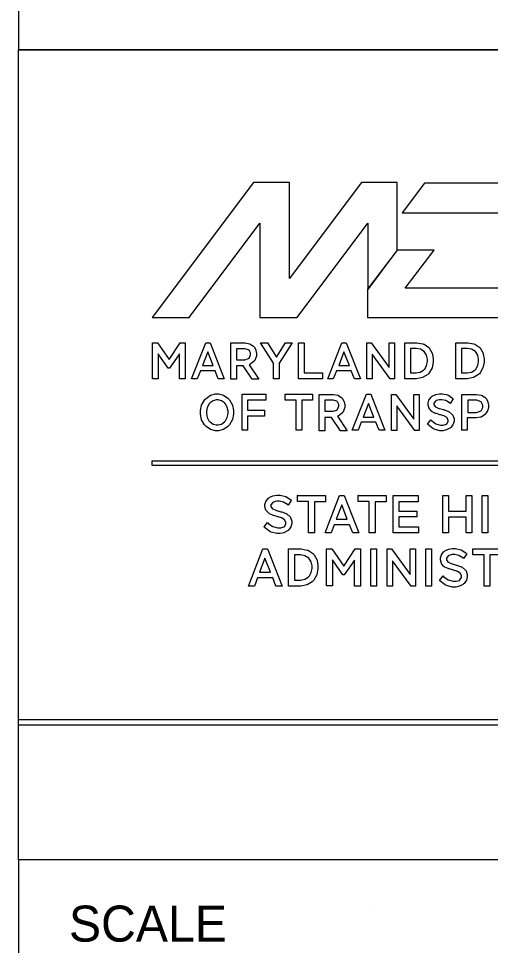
# Model space of a CAD drawing. Extents: x 0 to 34, y 0 to 22.
# Drawn here: x 27.437 to 28.747, y 2.513 to 5.087 of the extents above; entities that cross this region are included whole.
import ezdxf

# ---------------------------------------------------------------- set-up
doc = ezdxf.new("R2010")
doc.units = 0
for name, color, linetype in [('BORD-LINE', 7, 'Continuous'), ('MSHA-LOGO', 7, 'Continuous'), ('QNTY-LINE', 7, 'Continuous'), ('TTLB-TEXT', 7, 'Continuous'), ('USER-LINE', 7, 'Continuous')]:
    doc.layers.add(name, color=color, linetype=linetype)

msp = doc.modelspace()

# ---------------------------------------------------------------- linework, layer by layer
at = {"layer": 'BORD-LINE'}
for p, q in [((33.5, 5), (27.437, 5)), ((27.437, 2.75), (27.437, 5)), ((27.437, 2.75), (27.437, 0.75)), ((33.5, 2.75), (27.437, 2.75))]:
    msp.add_line(p, q, dxfattribs=at)
msp.add_lwpolyline([(27.437, 2.75), (27.437, 3.125), (33.5, 3.125)], dxfattribs=at)
at = {"layer": 'MSHA-LOGO'}
for points in [[(28.4067, 4.3335), (28.4886, 4.4423), (28.4886, 4.631), (28.389, 4.631), (28.3274, 4.5486), (28.189, 4.3646), (28.189, 4.631), (28.0895, 4.631), (27.8081, 4.2568), (27.9107, 4.2568), (28.1071, 4.518), (28.1071, 4.2568), (28.2102, 4.2568), (28.4067, 4.518)], [(27.8086, 4.1863), (27.8226, 4.1863), (27.8547, 4.1397), (27.8858, 4.1863), (27.8993, 4.1863), (27.8993, 4.0863), (27.8838, 4.0863), (27.8838, 4.1557), (27.8563, 4.1158), (27.8521, 4.1158), (27.8242, 4.1557), (27.8242, 4.0863), (27.8086, 4.0863)], [(27.9568, 4.1863), (27.9688, 4.1863), (28.0081, 4.0863), (27.9916, 4.0863), (27.9827, 4.1086), (27.9418, 4.1086), (27.933, 4.0863), (27.9169, 4.0863)], [(28.0263, 4.0858), (28.0263, 4.1858), (28.0615, 4.1858), (28.0659, 4.1858), (28.0779, 4.1836), (28.0792, 4.1832), (28.0803, 4.1828), (28.0894, 4.1767), (28.09, 4.176), (28.0907, 4.1752), (28.0953, 4.167), (28.0957, 4.1661), (28.096, 4.1652), (28.0973, 4.1569), (28.0973, 4.1542), (28.0973, 4.1497), (28.093, 4.1374), (28.0921, 4.1361), (28.0912, 4.1348), (28.0791, 4.1257), (28.0776, 4.1252), (28.1045, 4.0853), (28.0854, 4.0853), (28.061, 4.122), (28.0418, 4.122), (28.0418, 4.0853), (28.0263, 4.0853)], [(28.1605, 4.1293), (28.1605, 4.0858), (28.145, 4.0858), (28.145, 4.1293), (28.1087, 4.1863), (28.1278, 4.1863), (28.1527, 4.1464), (28.1781, 4.1863), (28.1968, 4.1863)], [(28.2144, 4.1863), (28.23, 4.1863), (28.23, 4.1024), (28.2813, 4.1024), (28.2813, 4.0863), (28.2144, 4.0863)], [(28.3346, 4.1863), (28.3466, 4.1863), (28.3859, 4.0863), (28.3694, 4.0863), (28.3605, 4.1086), (28.3196, 4.1086), (28.3108, 4.0863), (28.2952, 4.0863)], [(28.4689, 4.0858), (28.4191, 4.1542), (28.4191, 4.0858), (28.4041, 4.0858), (28.4041, 4.1858), (28.416, 4.1858), (28.4658, 4.1174), (28.4658, 4.1858), (28.4808, 4.1858), (28.4808, 4.0858)], [(28.5093, 4.1863), (28.5373, 4.1863), (28.5432, 4.1863), (28.5594, 4.1833), (28.5611, 4.1827), (28.5628, 4.1821), (28.5761, 4.173), (28.5772, 4.1718), (28.5781, 4.1707), (28.5851, 4.1577), (28.5855, 4.1563), (28.5858, 4.1548), (28.5881, 4.1419), (28.5881, 4.1376), (28.5881, 4.1325), (28.5849, 4.117), (28.5773, 4.1028), (28.5751, 4.1003), (28.5729, 4.098), (28.5587, 4.0898), (28.5415, 4.0863), (28.5357, 4.0863), (28.5093, 4.0863)], [(28.5248, 4.1697), (28.5248, 4.1024), (28.5367, 4.1024), (28.5406, 4.1024), (28.5523, 4.1047), (28.5617, 4.1101), (28.5632, 4.1117), (28.5646, 4.1133), (28.5697, 4.1229), (28.572, 4.1339), (28.572, 4.1376), (28.572, 4.1412), (28.5698, 4.1519), (28.5634, 4.1621), (28.5525, 4.1682), (28.5411, 4.1703), (28.5373, 4.1703), (28.5248, 4.1703)], [(28.6508, 4.1863), (28.6787, 4.1863), (28.6847, 4.1863), (28.7009, 4.1833), (28.7026, 4.1827), (28.7042, 4.1821), (28.7176, 4.173), (28.7186, 4.1718), (28.7195, 4.1707), (28.7265, 4.1577), (28.727, 4.1563), (28.7273, 4.1548), (28.7295, 4.1419), (28.7295, 4.1376), (28.7295, 4.1325), (28.7264, 4.117), (28.7188, 4.1028), (28.7166, 4.1003), (28.7144, 4.098), (28.7002, 4.0898), (28.6829, 4.0863), (28.6772, 4.0863), (28.6508, 4.0863)], [(28.6668, 4.1697), (28.6668, 4.1024), (28.6787, 4.1024), (28.6826, 4.1024), (28.6943, 4.1047), (28.7037, 4.1101), (28.7052, 4.1117), (28.7066, 4.1133), (28.7117, 4.1229), (28.714, 4.1339), (28.714, 4.1376), (28.714, 4.1412), (28.7118, 4.1519), (28.7054, 4.1621), (28.6945, 4.1682), (28.6831, 4.1703), (28.6793, 4.1703), (28.6668, 4.1703)], [(27.948, 4.1231), (27.9776, 4.1231), (27.9625, 4.1609)], [(28.0418, 4.1697), (28.0418, 4.1392), (28.062, 4.1392), (28.0655, 4.1392), (28.0751, 4.1427), (28.076, 4.1433), (28.0768, 4.144), (28.0812, 4.1524), (28.0812, 4.1552), (28.0812, 4.1579), (28.0773, 4.1654), (28.0766, 4.1661), (28.0758, 4.1667), (28.0651, 4.1697), (28.0615, 4.1697)], [(28.3258, 4.1231), (28.3554, 4.1231), (28.3403, 4.1609)], [(27.9553, 4.0293), (27.9575, 4.0318), (27.97, 4.0405), (27.9834, 4.0443), (27.9879, 4.0443), (27.9924, 4.0443), (28.0058, 4.0408), (28.0184, 4.0323), (28.0206, 4.0298), (28.0228, 4.0274), (28.0306, 4.0134), (28.034, 3.9981), (28.034, 3.993), (28.034, 3.988), (28.0306, 3.9729), (28.0228, 3.9587), (28.0206, 3.9562), (28.0184, 3.9538), (28.0058, 3.9453), (27.9924, 3.9417), (27.9879, 3.9417), (27.9834, 3.9417), (27.97, 3.9453), (27.9575, 3.9538), (27.9553, 3.9562), (27.9531, 3.9587), (27.9452, 3.9727), (27.9418, 3.988), (27.9418, 3.993), (27.9418, 3.998), (27.9452, 4.0129), (27.9531, 4.0268)], [(28.0574, 4.0433), (28.1237, 4.0433), (28.1237, 4.0272), (28.0729, 4.0272), (28.0729, 3.9987), (28.1201, 3.9987), (28.1201, 3.9827), (28.0729, 3.9827), (28.0729, 3.9433), (28.0574, 3.9433)], [(28.1771, 4.0433), (28.2533, 4.0433), (28.2533, 4.0272), (28.2232, 4.0272), (28.2232, 3.9433), (28.2077, 3.9433), (28.2077, 4.0272), (28.1776, 4.0272), (28.1776, 4.0433)], [(28.2714, 3.9427), (28.2714, 4.0428), (28.3066, 4.0428), (28.311, 4.0428), (28.323, 4.0406), (28.3243, 4.0402), (28.3254, 4.0398), (28.3345, 4.0337), (28.3351, 4.0329), (28.3358, 4.0322), (28.3405, 4.024), (28.3409, 4.0231), (28.3412, 4.0222), (28.3424, 4.0139), (28.3424, 4.0112), (28.3424, 4.0066), (28.3381, 3.9943), (28.3372, 3.993), (28.3363, 3.9917), (28.3243, 3.9827), (28.3227, 3.9821), (28.3497, 3.9422), (28.3305, 3.9422), (28.3061, 3.979), (28.287, 3.979), (28.287, 3.9422), (28.2714, 3.9422)], [(28.4031, 4.0433), (28.415, 4.0433), (28.4543, 3.9433), (28.4378, 3.9433), (28.429, 3.9655), (28.3885, 3.9655), (28.3797, 3.9433), (28.3636, 3.9433)], [(28.5373, 3.9427), (28.4875, 4.0112), (28.4875, 3.9427), (28.4725, 3.9427), (28.4725, 4.0428), (28.4844, 4.0428), (28.5341, 3.9744), (28.5341, 4.0428), (28.5492, 4.0428), (28.5492, 3.9427)], [(28.6264, 3.978), (28.6259, 3.9785), (28.6194, 3.9828), (28.6186, 3.9832), (28.6179, 3.9834), (28.6088, 3.986), (28.6078, 3.9863), (28.6067, 3.9865), (28.5969, 3.9895), (28.5958, 3.9899), (28.5948, 3.9903), (28.5857, 3.9946), (28.5849, 3.9951), (28.5842, 3.9956), (28.5777, 4.0025), (28.5772, 4.0034), (28.5766, 4.0043), (28.5741, 4.0134), (28.5741, 4.0163), (28.5741, 4.0191), (28.5764, 4.0272), (28.5822, 4.0351), (28.5839, 4.0365), (28.5856, 4.038), (28.5952, 4.0429), (28.6058, 4.0449), (28.6093, 4.0449), (28.6143, 4.0449), (28.6292, 4.0413), (28.642, 4.0328), (28.644, 4.0303), (28.6357, 4.0179), (28.6338, 4.0196), (28.6232, 4.0256), (28.6124, 4.0283), (28.6088, 4.0283), (28.6054, 4.0283), (28.5962, 4.0257), (28.5953, 4.0251), (28.5944, 4.0246), (28.5901, 4.0184), (28.5901, 4.0163), (28.5901, 4.0144), (28.5936, 4.0091), (28.5943, 4.0086), (28.5949, 4.0081), (28.6036, 4.0042), (28.6046, 4.0039), (28.6057, 4.0037), (28.6169, 4.0007), (28.6181, 4.0003), (28.6193, 3.9999), (28.6305, 3.9956), (28.6316, 3.9951), (28.6326, 3.9946), (28.6413, 3.9873), (28.642, 3.9863), (28.6426, 3.9853), (28.6461, 3.9751), (28.6461, 3.9718), (28.6461, 3.9688), (28.6437, 3.96), (28.6379, 3.9519), (28.6363, 3.9505), (28.6346, 3.9491), (28.625, 3.9443), (28.6152, 3.9422), (28.6119, 3.9422), (28.6062, 3.9422), (28.5909, 3.9465), (28.5891, 3.9474), (28.5873, 3.9483), (28.573, 3.9591), (28.572, 3.9604), (28.5813, 3.9723), (28.5834, 3.97), (28.5954, 3.9616), (28.6085, 3.9578), (28.6129, 3.9578), (28.616, 3.9578), (28.6247, 3.9604), (28.6254, 3.9609), (28.6261, 3.9614), (28.63, 3.9677), (28.63, 3.9697), (28.6299, 3.9706), (28.6269, 3.9775)], [(28.6679, 3.9427), (28.6679, 4.0428), (28.7041, 4.0428), (28.7088, 4.0428), (28.7215, 4.0406), (28.7228, 4.0402), (28.7241, 4.0397), (28.7335, 4.0332), (28.7342, 4.0324), (28.7348, 4.0317), (28.7396, 4.023), (28.7399, 4.022), (28.7402, 4.0212), (28.7414, 4.0129), (28.7414, 4.0101), (28.7414, 4.0071), (28.7397, 3.9991), (28.7394, 3.9982), (28.739, 3.9973), (28.7338, 3.9886), (28.7332, 3.9878), (28.7325, 3.9871), (28.7225, 3.9806), (28.7212, 3.9801), (28.7199, 3.9796), (28.7077, 3.9775), (28.7036, 3.9775), (28.6829, 3.9775), (28.6829, 3.9433), (28.6679, 3.9433)], [(27.9672, 3.9681), (27.9686, 3.9665), (27.9769, 3.9607), (27.9855, 3.9583), (27.9885, 3.9583), (27.9913, 3.9583), (28, 3.9607), (28.0083, 3.9665), (28.0097, 3.9681), (28.0111, 3.9697), (28.0162, 3.979), (28.0185, 3.9895), (28.0185, 3.993), (28.0185, 3.9965), (28.0162, 4.007), (28.0111, 4.0163), (28.0097, 4.0179), (28.0083, 4.0196), (28, 4.0254), (27.9913, 4.0277), (27.9885, 4.0277), (27.9855, 4.0277), (27.9769, 4.0254), (27.9686, 4.0196), (27.9672, 4.0179), (27.9658, 4.0163), (27.9606, 4.007), (27.9584, 3.9965), (27.9584, 3.993), (27.9584, 3.9895), (27.9604, 3.979), (27.9656, 3.9697)], [(28.287, 4.0267), (28.287, 3.9961), (28.3072, 3.9961), (28.3107, 3.9961), (28.3202, 3.9996), (28.3212, 4.0003), (28.3219, 4.0009), (28.3263, 4.0094), (28.3263, 4.0122), (28.3263, 4.0149), (28.3224, 4.0224), (28.3217, 4.0231), (28.3209, 4.0237), (28.3102, 4.0267), (28.3066, 4.0267)], [(28.3942, 3.9801), (28.4238, 3.9801), (28.4088, 4.0179)], [(28.6839, 4.0267), (28.6839, 3.993), (28.7047, 3.993), (28.7087, 3.993), (28.721, 3.9973), (28.7264, 4.0069), (28.7264, 4.0101), (28.7264, 4.0132), (28.7213, 4.0225), (28.7096, 4.0267), (28.7057, 4.0267)], [(27.8081, 3.8588), (29.6017, 3.8588), (29.6017, 3.8458), (27.8081, 3.8458)], [(28.1761, 3.6945), (28.1755, 3.695), (28.1687, 3.6993), (28.1678, 3.6997), (28.1668, 3.7), (28.1574, 3.7031), (28.1563, 3.7033), (28.1553, 3.7036), (28.145, 3.7066), (28.1439, 3.7069), (28.1429, 3.7073), (28.1334, 3.7116), (28.1325, 3.7121), (28.1316, 3.7127), (28.1247, 3.7201), (28.1242, 3.7209), (28.1237, 3.7219), (28.1211, 3.7313), (28.1211, 3.7344), (28.1211, 3.7373), (28.1238, 3.7458), (28.1298, 3.7537), (28.1315, 3.7551), (28.1332, 3.7566), (28.1431, 3.7614), (28.1542, 3.7634), (28.1579, 3.7634), (28.1631, 3.7634), (28.1786, 3.7596), (28.192, 3.7509), (28.1942, 3.7484), (28.1854, 3.7354), (28.1834, 3.7373), (28.1725, 3.7436), (28.1612, 3.7463), (28.1574, 3.7463), (28.1539, 3.7463), (28.1443, 3.7438), (28.1434, 3.7432), (28.1425, 3.7427), (28.1377, 3.7361), (28.1377, 3.7339), (28.1377, 3.7318), (28.1412, 3.7262), (28.1419, 3.7256), (28.1425, 3.7251), (28.1515, 3.7212), (28.1527, 3.7209), (28.1539, 3.7207), (28.1654, 3.7172), (28.1667, 3.7168), (28.168, 3.7164), (28.1797, 3.712), (28.1807, 3.7116), (28.1817, 3.7111), (28.1908, 3.7033), (28.1916, 3.7023), (28.1922, 3.7012), (28.1958, 3.6908), (28.1958, 3.6873), (28.1958, 3.6842), (28.1931, 3.675), (28.1871, 3.6664), (28.1854, 3.665), (28.1837, 3.6636), (28.1738, 3.6584), (28.1634, 3.6562), (28.16, 3.6562), (28.154, 3.6562), (28.1381, 3.6605), (28.1362, 3.6614), (28.1342, 3.6623), (28.1196, 3.6735), (28.1185, 3.6748), (28.1284, 3.6873), (28.1304, 3.6848), (28.1428, 3.6761), (28.1568, 3.6722), (28.1615, 3.6722), (28.1648, 3.6722), (28.1737, 3.6748), (28.1745, 3.6753), (28.1753, 3.6759), (28.1792, 3.6825), (28.1792, 3.6847), (28.1792, 3.6871), (28.1766, 3.694)], [(28.2108, 3.7619), (28.2896, 3.7619), (28.2896, 3.7448), (28.2585, 3.7448), (28.2585, 3.6582), (28.2424, 3.6582), (28.2424, 3.7453), (28.2113, 3.7453), (28.2113, 3.7619)], [(28.3284, 3.7619), (28.3409, 3.7619), (28.3818, 3.6582), (28.3647, 3.6582), (28.3559, 3.681), (28.3134, 3.681), (28.3046, 3.6582), (28.288, 3.6582)], [(28.3792, 3.7619), (28.458, 3.7619), (28.458, 3.7448), (28.4269, 3.7448), (28.4269, 3.6582), (28.4108, 3.6582), (28.4108, 3.7453), (28.3797, 3.7453), (28.3797, 3.7619)], [(28.4766, 3.7619), (28.5461, 3.7619), (28.5461, 3.7448), (28.4927, 3.7448), (28.4927, 3.7189), (28.5424, 3.7189), (28.5424, 3.7028), (28.4927, 3.7028), (28.4927, 3.6753), (28.5471, 3.6753), (28.5471, 3.6582), (28.4766, 3.6582)], [(28.6793, 3.7023), (28.6305, 3.7023), (28.6305, 3.6582), (28.6145, 3.6582), (28.6145, 3.7619), (28.6305, 3.7619), (28.6305, 3.7189), (28.6793, 3.7189), (28.6793, 3.7619), (28.6953, 3.7619), (28.6953, 3.6582), (28.6793, 3.6582)], [(28.7238, 3.7619), (28.7399, 3.7619), (28.7399, 3.6582), (28.7238, 3.6582)], [(28.3191, 3.6966), (28.3497, 3.6966), (28.3341, 3.736)], [(28.1154, 3.6142), (28.1278, 3.6142), (28.1688, 3.5105), (28.1517, 3.5105), (28.1429, 3.5333), (28.1004, 3.5333), (28.0916, 3.5105), (28.075, 3.5105)], [(28.1869, 3.6142), (28.2159, 3.6142), (28.222, 3.6142), (28.2386, 3.6107), (28.2403, 3.61), (28.242, 3.6094), (28.2558, 3.5999), (28.2569, 3.5986), (28.2579, 3.5975), (28.2652, 3.5841), (28.2657, 3.5826), (28.2662, 3.581), (28.2683, 3.5678), (28.2683, 3.5634), (28.2683, 3.5581), (28.2649, 3.5421), (28.257, 3.5275), (28.2548, 3.525), (28.2526, 3.5226), (28.2379, 3.5141), (28.2203, 3.5105), (28.2144, 3.5105), (28.1869, 3.5105)], [(28.2921, 3.6142), (28.3066, 3.6142), (28.3398, 3.566), (28.372, 3.6142), (28.3859, 3.6142), (28.3859, 3.5105), (28.3699, 3.5105), (28.3699, 3.5826), (28.3414, 3.5416), (28.3372, 3.5416), (28.3082, 3.5831), (28.3082, 3.5111), (28.2921, 3.5111)], [(28.415, 3.6142), (28.431, 3.6142), (28.431, 3.5105), (28.415, 3.5105)], [(28.5269, 3.5105), (28.4756, 3.581), (28.4756, 3.5105), (28.4601, 3.5105), (28.4601, 3.6142), (28.4725, 3.6142), (28.5238, 3.5432), (28.5238, 3.6142), (28.5393, 3.6142), (28.5393, 3.5105)], [(28.5678, 3.6142), (28.5839, 3.6142), (28.5839, 3.5105), (28.5678, 3.5105)], [(28.6632, 3.5463), (28.6627, 3.5468), (28.6558, 3.5511), (28.6549, 3.5515), (28.654, 3.5517), (28.6445, 3.5549), (28.6435, 3.5551), (28.6424, 3.5554), (28.6321, 3.5584), (28.6311, 3.5587), (28.63, 3.5591), (28.6206, 3.5634), (28.6197, 3.5639), (28.6187, 3.5645), (28.6119, 3.5718), (28.6114, 3.5727), (28.6108, 3.5736), (28.6083, 3.5831), (28.6083, 3.5862), (28.6083, 3.589), (28.6109, 3.5975), (28.6169, 3.6055), (28.6186, 3.6069), (28.6203, 3.6084), (28.6303, 3.6132), (28.6414, 3.6152), (28.6451, 3.6152), (28.6502, 3.6152), (28.6657, 3.6114), (28.6791, 3.6027), (28.6813, 3.6002), (28.6725, 3.5872), (28.6706, 3.5891), (28.6597, 3.5954), (28.6483, 3.5981), (28.6445, 3.5981), (28.641, 3.5981), (28.6314, 3.5955), (28.6305, 3.595), (28.6296, 3.5945), (28.6248, 3.5879), (28.6248, 3.5857), (28.6248, 3.5836), (28.6284, 3.578), (28.629, 3.5774), (28.6297, 3.5769), (28.6387, 3.573), (28.6399, 3.5727), (28.641, 3.5725), (28.6526, 3.569), (28.6539, 3.5686), (28.6552, 3.5682), (28.6668, 3.5638), (28.6679, 3.5634), (28.6689, 3.5629), (28.678, 3.5551), (28.6787, 3.5541), (28.6794, 3.553), (28.6829, 3.5425), (28.6829, 3.539), (28.6829, 3.536), (28.6802, 3.5267), (28.6742, 3.5182), (28.6725, 3.5168), (28.6708, 3.5154), (28.661, 3.5102), (28.6506, 3.5079), (28.6471, 3.5079), (28.6412, 3.5079), (28.6252, 3.5122), (28.6233, 3.5131), (28.6214, 3.514), (28.6067, 3.5253), (28.6057, 3.5266), (28.6155, 3.539), (28.6176, 3.5366), (28.6299, 3.5279), (28.644, 3.524), (28.6487, 3.524), (28.6519, 3.524), (28.6609, 3.5266), (28.6616, 3.5271), (28.6624, 3.5277), (28.6663, 3.5342), (28.6663, 3.5364), (28.6663, 3.5389), (28.6637, 3.5458)], [(28.6979, 3.6142), (28.7767, 3.6142), (28.7767, 3.5971), (28.7456, 3.5971), (28.7456, 3.5105), (28.7295, 3.5105), (28.7295, 3.5971), (28.6985, 3.5971), (28.6985, 3.6142)], [(28.1061, 3.5489), (28.1367, 3.5489), (28.1211, 3.5883)], [(28.203, 3.5971), (28.203, 3.5271), (28.2154, 3.5271), (28.2194, 3.5271), (28.2315, 3.5295), (28.2413, 3.5353), (28.2429, 3.537), (28.2444, 3.5387), (28.2496, 3.5486), (28.2517, 3.5597), (28.2517, 3.5634), (28.2517, 3.5671), (28.2495, 3.5781), (28.2428, 3.5886), (28.2316, 3.595), (28.2198, 3.5971), (28.2159, 3.5971)]]:
    msp.add_lwpolyline(points, close=True, dxfattribs=at)
for points in [[(28.8109, 4.6294), (28.5637, 4.6294), (28.502, 4.5475), (28.8109, 4.5475)], [(28.8109, 4.3382), (28.5108, 4.3382), (28.5906, 4.4434), (28.488, 4.4434), (28.4062, 4.3351), (28.4062, 4.2563), (28.8104, 4.2563)]]:
    msp.add_lwpolyline(points, dxfattribs=at)
at = {"layer": 'QNTY-LINE'}
msp.add_line((27.4369, 21.5), (27.437, 5), dxfattribs=at)
at = {"layer": 'TTLB-TEXT'}
msp.add_line((28.4263, 2.6233), (28.4263, 2.6233), dxfattribs=at)
at = {"layer": 'USER-LINE'}
msp.add_lwpolyline([(27.437, 5), (30.0454, 5), (30.0454, 3.1389), (27.437, 3.1389)], close=True, dxfattribs=at)

# ---------------------------------------------------------------- texts
at = {"layer": 'TTLB-TEXT'}
msp.add_text('SCALE', height=0.1, dxfattribs=at).set_placement((27.5769, 2.5233))

doc.saveas('drawing.dxf')
